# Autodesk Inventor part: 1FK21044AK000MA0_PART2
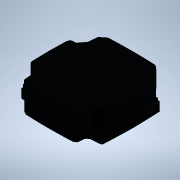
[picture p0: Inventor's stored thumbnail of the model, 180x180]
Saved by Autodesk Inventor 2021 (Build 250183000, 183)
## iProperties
Created: 2025-04
Part Number: 1FK21044AK000MA0_PART2
Material: Generic
Catalog Web Link: www.3dfindit.com
Description: -Servo synchronous motor
Document SubType Name: Modeling
Designer: psAdmin
Mass: 135.825 g
Surface Area: 188.795 cm^2
Volume: 135.825 cm^3
Density: 1 g/cm^3
Appearance: PSOLRGB-38-46-56
Category: PARTsolutions
Title: 1FK21044AK000MA0_PART2
Author: Cadenas PARTsolutions
Comments: Servo synchronous motor
Sending System: PARTsolutions
Preprocessor: ST-DEVELOPER v19.3
PSOL_IDENT_0: {$CADENAS_DATA/23d-libs/siemens_ag/_cat_/87/f4/1fk21044ak000ma0.prj},213 {VTYP=3D},{NB=1FK21044AK000
PSOL_IDENT_1: MA0_PART2},{LINA=1FK21044AK000MA0_PART2},{NN=1FK21044AK000MA0_PART2},{NOPRJ=TRUE},{DATE=19.08.2025 1
PSOL_IDENT_2: 4:00:48},{GEOMDATE=30.07.2025 02:00:50},{VERSION=},{LINEID=10},{WBVAR=},{WBNUMERIC=}  {NB=1FK21044AK
PSOL_IDENT_3: 000MA0_PART2},{LINA=1FK21044AK000MA0_PART2},{KT=DUMMY},{PREVIEW=../../../_pool_/cb/72/p_d211_xx_0043
PSOL_IDENT_4: 4j.png},{DESCSHORT=SIMOTICS S-1FK2 HD, SINAMICS S210 3AC 400V-480V, 0.95 Nm, 6000 rpm},{DESCLONG=SIM
PSOL_IDENT_5: OTICS S-1FK2 HD servo motor M0=1.27 Nm; PN = 0.6 kW at nN=6000 rpm (380-480 V); PN = 0.4 kW at nN=30
PSOL_IDENT_6: 00 rpm (200-240 V); degree of protection IP64; cylindrical shaft D19x40mm; absolute encoder 22-bit +
PSOL_IDENT_7: 12-bit multiturn (encoder AM22DQC); with OCC interface; plug size M17, rotatable; SIMOTICS S-1FK2 s
PSOL_IDENT_8: ervomotorfor a wide range of uses in industrial environments. SIMOTICS S‑1FK2 servomotors are compac
PSOL_IDENT_9: t synchronous motors with a high dynamic performance that set themselves apart as a result of their
PSOL_IDENT_10: high power density, degree of protection and overload capability. The motors are available in two va
PSOL_IDENT_11: riants: as High Dynamic variant (highest dynamic performance as a result of the low intrinsic moment
PSOL_IDENT_12: of inertia for applications demanding a high dynamic performance with low moved masses) - and as Co
PSOL_IDENT_13: mpact variant (precise and stable closed-loop control for medium up to large moved masses as a resul
PSOL_IDENT_14: t of a medium intrinsic moment of inertia). SIMOTICSS‑1FK2 servomotors fully exploit their strengths
PSOL_IDENT_15: in a system with the SINAMICSS210 frequency converter and simple connection using the one cable con
PSOL_IDENT_16: nection (OCC). Advantages include the short control and positioning times, fast and precise correcti
PSOL_IDENT_17: on of disturbing quantities as well as stable control with a high dynamic performance. The servo mot
PSOL_IDENT_18: ors can be configured to address a wide range of requirements. For example with and without holding
PSOL_IDENT_19: brake, IP64 or IP65 degree of protection, singleturn or multiturn absolute encoders - to name just a
PSOL_IDENT_20: few. Further, the servomotors are available in different shaft heights extending from 20 to 100. A
PSOL_IDENT_21: shaft sealing ring is available to achieve an IP65 degree of protection and for subsequent mounting
PSOL_IDENT_22: at the motor or as spare part. SIMOTICS - the optimum motor for each and every motion control applic
PSOL_IDENT_23: ation.},{INTNO=195125056312},{SUPPLIERALTNO=1FK2104-4AK00-0MA0},{MANUID=1FK21044AK000MA0},{MANUNAME=
PSOL_IDENT_24: Siemens},{MANUTYPEDESC=Synchronous motor 1FK2-HD 1,27 Nm},{AAU732=SIMOTICS},{AAO057=S-1FK2},{AAU734=
PSOL_IDENT_25: SIMOTICS S-1FK2 HD servo motor M0=1.27 Nm; PN = 0.6 kW at nN=6000 rpm (380-480 V); PN = 0.4 kW at nN=
PSOL_IDENT_26: 3000 rpm (200-240 V); degree of protection IP64; cylindrical shaft D19x40mm; absolute encoder 22-bit
PSOL_IDENT_27: + 12-bit multiturn (encoder AM22DQC); with OCC interface; plug size M17, rotatable;},{AAW338=Synchr
PSOL_IDENT_28: onous motor 1FK2-HD 1,27 Nm},{AAO742=SIMOTICS},{AAO663=4042948690994},{NOCUPEROU=1},{PRICEQUANTITY=1
PSOL_IDENT_29: },{QUANTITYMIN=1},{QUANTITYINT=1},{CTN=85015100},{COO=DE},{AAO676=1FK2104-4AK00-0MA0},{AAO677=Siemen
PSOL_IDENT_30: s AG},{ORDERUNIT=C62},{CONTENTUNIT=C62}
NB: 1FK21044AK000MA0_PART2
NT: Servo synchronous motor
NBSYN: $MANUID._PART2
LINA: 1FK21044AK000MA0_PART2
CATALOG: SIEMENS
PREVIEW: ../../../_pool_/cb/72/p_d211_xx_00434j.png
DESCSHORT: SIMOTICS S-1FK2 HD, SINAMICS S210 3AC 400V-480V, 0.95 Nm, 6000 rpm
DESCLONG: SIMOTICS S-1FK2 HD servo motor M0=1.27 Nm; PN = 0.6 kW at nN=6000 rpm (380-480 V); PN = 0.4 kW at nN=3000 rpm (200-240 V); degree of protection IP64; cylindrica
INTNO: 195125056312
SUPPLIERALTNO: 1FK2104-4AK00-0MA0
MANUID: 1FK21044AK000MA0
MANUNAME: Siemens
MANUTYPEDESC: Synchronous motor 1FK2-HD 1,27 Nm
AAU732: SIMOTICS
AAO057: S-1FK2
AAU734: SIMOTICS S-1FK2 HD servo motor M0=1.27 Nm; PN = 0.6 kW at nN=6000 rpm (380-480 V); PN = 0.4 kW at nN=3000 rpm (200-240 V); degree of protection IP64; cylindrica
AAW338: Synchronous motor 1FK2-HD 1,27 Nm
AAO742: SIMOTICS
AAO663: 4042948690994.0
NOCUPEROU: 1
PRICEQUANTITY: 1
QUANTITYMIN: 1
QUANTITYINT: 1
CTN: 85015100
COO: DE
ARTICLENO: 1FK21044AK000MA0_PART2
BOMINFO: 1FK21044AK000MA0_PART2
CREATOR: CADENAS GmbH
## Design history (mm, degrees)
feature "2025_04_17_15_37_40_0463"
body "Solid1"
